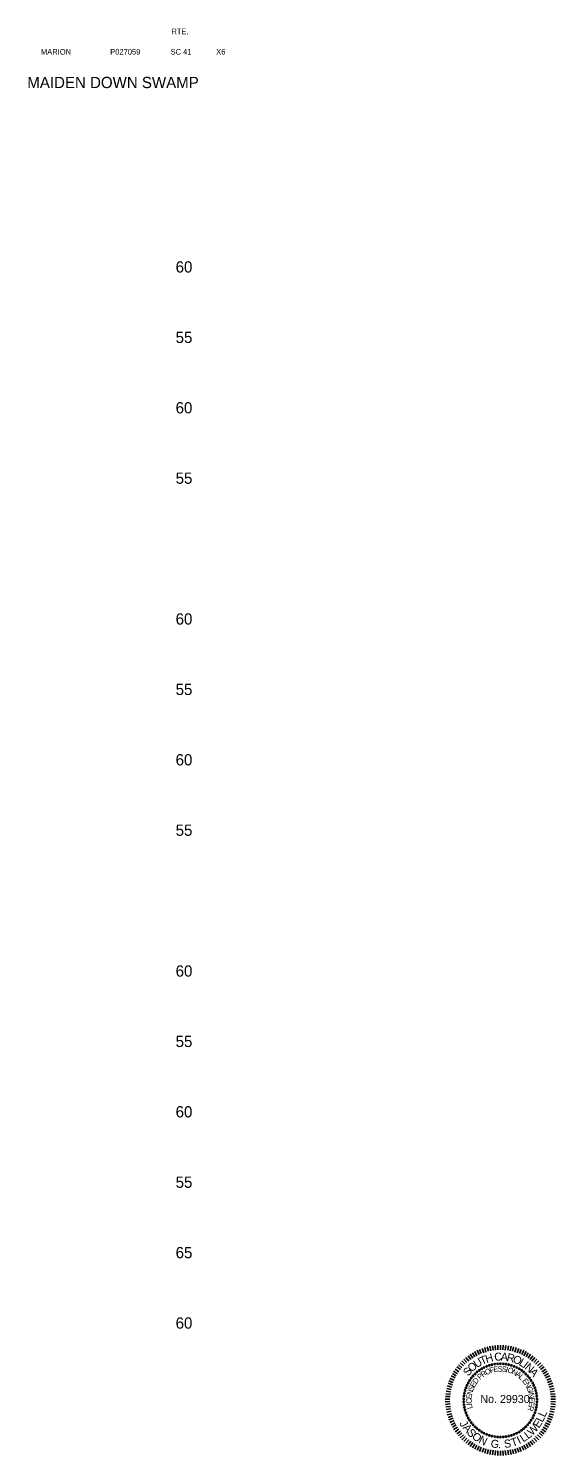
# Model space of a CAD drawing. Extents: x 1001 to 1184, y 1001 to 1447.
# Drawn here: x 1146.5 to 1183.9, y 1001 to 1102.3 of the extents above; entities that cross this region are included whole.
import ezdxf

# ---------------------------------------------------------------- set-up
doc = ezdxf.new("R2010")
doc.units = 0
for name, color, linetype in [('RD_HC_Cl', 7, 'Continuous'), ('RD_SHT_TX', 7, 'Continuous'), ('RD_TX_PEShield', 7, 'Continuous'), ('RD_XS_TX_Elev_EX', 7, 'Continuous')]:
    doc.layers.add(name, color=color, linetype=linetype)

# ---------------------------------------------------------------- blocks, each defined once
blk = doc.blocks.new('STILLWELL')
at = {"layer": 'RD_TX_PEShield'}
for p, q in [((-21.1, 28.1), (-23, 30.7)), ((-19.7, 29.1), (-21.5, 31.8)), ((-18.2, 30), (-19.9, 32.8)), ((-16.7, 30.8), (-18.2, 33.7)), ((-15.1, 31.6), (-16.5, 34.6)), ((-13.6, 32.3), (-14.8, 35.3)), ((-11.9, 32.9), (-13, 36)), ((-10.3, 33.4), (-11.2, 36.6)), ((-8.6, 33.9), (-9.4, 37.1)), ((-6.9, 34.3), (-7.5, 37.5)), ((-5.2, 34.6), (-5.7, 37.8)), ((-3.5, 34.8), (-3.8, 38)), ((-1.8, 34.9), (-1.9, 38.2)), ((0, 34.9), (0, 38.2)), ((1.7, 34.9), (1.9, 38.2)), ((3.4, 34.8), (3.7, 38)), ((5.2, 34.6), (5.6, 37.8)), ((6.9, 34.3), (7.5, 37.5)), ((8.6, 33.9), (9.3, 37.1)), ((10.2, 33.4), (11.2, 36.6)), ((11.9, 32.9), (13, 36)), ((13.5, 32.3), (14.7, 35.3)), ((15.1, 31.6), (16.5, 34.6)), ((16.6, 30.8), (18.2, 33.7)), ((18.2, 30), (19.8, 32.8)), ((19.6, 29.1), (21.4, 31.8)), ((21.1, 28.1), (23, 30.7)), ((-29.5, 19.4), (-32.2, 21.3)), ((-28.5, 20.9), (-31.1, 22.8)), ((-27.4, 22.2), (-29.9, 24.3)), ((-26.3, 23.5), (-28.7, 25.7)), ((-25.1, 24.7), (-27.4, 27.1)), ((-23.8, 25.9), (-26, 28.4)), ((-22.5, 27), (-24.5, 29.6)), ((22.4, 27), (24.5, 29.6)), ((23.8, 25.9), (25.9, 28.4)), ((25, 24.7), (27.3, 27.1)), ((26.2, 23.5), (28.6, 25.7)), ((27.4, 22.2), (29.9, 24.3)), ((28.5, 20.9), (31.1, 22.8)), ((29.5, 19.4), (32.2, 21.3)), ((-34.1, 10.2), (-37.2, 11.2)), ((-33.6, 11.8), (-36.6, 12.9)), ((-32.9, 13.4), (-35.9, 14.7)), ((-32.2, 15), (-35.1, 16.4)), ((-31.4, 16.5), (-34.2, 18.1)), ((-30.5, 18), (-33.3, 19.7)), ((30.4, 18), (33.2, 19.7)), ((31.3, 16.5), (34.2, 18.1)), ((32.1, 15), (35.1, 16.4)), ((32.9, 13.4), (35.9, 14.7)), ((33.5, 11.8), (36.6, 12.9)), ((34.1, 10.2), (37.2, 11.2)), ((-35.9, -0.1), (-39.2, 0)), ((-35.8, 1.7), (-39.1, 1.9)), ((-35.6, 3.4), (-38.9, 3.8)), ((-35.4, 5.1), (-38.6, 5.7)), ((-35.1, 6.8), (-38.2, 7.5)), ((-34.6, 8.5), (-37.8, 9.4)), ((34.6, 8.5), (37.7, 9.4)), ((35, 6.8), (38.2, 7.5)), ((35.3, 5.1), (38.5, 5.7)), ((35.6, 3.4), (38.8, 3.8)), ((35.7, 1.7), (39, 1.9)), ((35.8, -0.1), (39.1, 0)), ((-35.9, -1.8), (-39.2, -1.9)), ((-35.8, -3.5), (-39.1, -3.8)), ((-35.6, -5.3), (-38.9, -5.6)), ((-35.4, -7), (-38.6, -7.5)), ((-35.1, -8.7), (-38.2, -9.4)), ((35, -8.7), (38.2, -9.4)), ((35.3, -7), (38.5, -7.5)), ((35.6, -5.3), (38.8, -5.6)), ((35.7, -3.5), (39, -3.8)), ((35.8, -1.8), (39.1, -1.9)), ((-34.6, -10.4), (-37.8, -11.2)), ((-34.1, -12), (-37.2, -13)), ((-33.6, -13.6), (-36.6, -14.8)), ((-32.9, -15.3), (-35.9, -16.6)), ((-32.2, -16.8), (-35.1, -18.3)), ((-31.4, -18.4), (-34.2, -19.9)), ((-30.5, -19.9), (-33.3, -21.6)), ((30.4, -19.9), (33.2, -21.6)), ((31.3, -18.4), (34.2, -19.9)), ((32.1, -16.8), (35.1, -18.3)), ((32.9, -15.3), (35.9, -16.6)), ((33.5, -13.6), (36.6, -14.8)), ((34.1, -12), (37.2, -13)), ((34.6, -10.4), (37.7, -11.2)), ((-29.5, -21.3), (-32.2, -23.2)), ((-28.5, -22.7), (-31.1, -24.7)), ((-27.4, -24.1), (-29.9, -26.2)), ((-26.3, -25.4), (-28.7, -27.6)), ((-25.1, -26.6), (-27.4, -28.9)), ((-23.8, -27.8), (-26, -30.2)), ((-22.5, -28.9), (-24.5, -31.4)), ((-21.1, -29.9), (-23, -32.6)), ((21.1, -29.9), (23, -32.6)), ((22.4, -28.9), (24.5, -31.4)), ((23.8, -27.8), (25.9, -30.2)), ((25, -26.6), (27.3, -28.9)), ((26.2, -25.4), (28.6, -27.6)), ((27.4, -24.1), (29.9, -26.2)), ((28.5, -22.7), (31.1, -24.7)), ((29.5, -21.3), (32.2, -23.2)), ((-19.7, -30.9), (-21.5, -33.7)), ((-18.2, -31.8), (-19.9, -34.7)), ((-16.7, -32.7), (-18.2, -35.6)), ((-15.1, -33.5), (-16.5, -36.4)), ((-13.6, -34.1), (-14.8, -37.2)), ((-11.9, -34.8), (-13, -37.8)), ((-10.3, -35.3), (-11.2, -38.4)), ((-8.6, -35.8), (-9.4, -38.9)), ((-6.9, -36.1), (-7.5, -39.3)), ((-5.2, -36.4), (-5.7, -39.7)), ((-3.5, -36.6), (-3.8, -39.9)), ((-1.8, -36.8), (-1.9, -40)), ((0, -36.8), (0, -40.1)), ((1.7, -36.8), (1.9, -40)), ((3.4, -36.6), (3.7, -39.9)), ((5.2, -36.4), (5.6, -39.7)), ((6.9, -36.1), (7.5, -39.3)), ((8.6, -35.8), (9.3, -38.9)), ((10.2, -35.3), (11.2, -38.4)), ((11.9, -34.8), (13, -37.8)), ((13.5, -34.1), (14.7, -37.2)), ((15.1, -33.5), (16.5, -36.4)), ((16.6, -32.7), (18.2, -35.6)), ((18.2, -31.8), (19.8, -34.7)), ((19.6, -30.9), (21.4, -33.7))]:
    blk.add_line(p, q, dxfattribs=at)
for centre in [(-15, 20.4), (-13.3, 21.5), (-11.6, 22.4), (-9.8, 23.2), (-7.9, 23.9), (-6, 24.4), (-4, 24.8), (-2, 25), (0, 25.1), (2, 25), (3.9, 24.8), (5.9, 24.4), (7.8, 23.9), (9.7, 23.2), (11.5, 22.4), (13.3, 21.5), (15, 20.4), (-23.8, 9.7), (-22.9, 11.5), (-21.9, 13.2), (-20.7, 14.9), (-19.5, 16.4), (-18.1, 17.8), (-16.6, 19.2), (16.5, 19.2), (18, 17.8), (19.4, 16.4), (20.7, 14.9), (21.8, 13.2), (22.9, 11.5), (23.7, 9.7), (-26.1, 0.1), (-25.9, 2.1), (-25.6, 4), (-25.1, 6), (-24.5, 7.9), (24.5, 7.9), (25.1, 6), (25.5, 4), (25.8, 2.1), (26, 0.1), (-26.1, -1.9), (-25.9, -3.9), (-25.6, -5.9), (-25.1, -7.8), (-24.5, -9.7), (24.5, -9.7), (25.1, -7.8), (25.5, -5.9), (25.8, -3.9), (26, -1.9), (-23.8, -11.6), (-22.9, -13.4), (-21.9, -15.1), (-20.7, -16.7), (-19.5, -18.3), (-18.1, -19.7), (18, -19.7), (19.4, -18.3), (20.7, -16.7), (21.8, -15.1), (22.9, -13.4), (23.7, -11.6), (-16.6, -21), (-15, -22.2), (-13.3, -23.3), (-11.6, -24.3), (-9.8, -25.1), (-7.9, -25.8), (-6, -26.3), (-4, -26.7), (-2, -26.9), (0, -27), (2, -26.9), (3.9, -26.7), (5.9, -26.3), (7.8, -25.8), (9.7, -25.1), (11.5, -24.3), (13.3, -23.3), (15, -22.2), (16.5, -21)]:
    blk.add_circle(centre, 0.49, dxfattribs=at)
for s, height, rotation, p in [('T', 5.68, 23.5044, (-13.2, 24.1)), ('H', 5.68, 16.1357, (-9.9, 25.6)), ('C', 5.68, 4.076, (-4.2, 27.1)), ('A', 5.68, 355.3651, (0.1, 27.4)), ('R', 5.68, 347.3188, (4.1, 27.1)), ('O', 5.68, 338.6079, (8.3, 26.2)), ('S', 5.68, 49.6435, (-22.9, 15.8)), ('O', 5.68, 41.5972, (-20.4, 18.8)), ('U', 5.68, 32.2152, (-16.9, 21.8)), ('O', 3.92, 24.9735, (-10, 16.9)), ('F', 3.92, 15.9995, (-7.1, 18.3)), ('E', 3.92, 8.9511, (-4.7, 19)), ('S', 3.92, 1.2546, (-1.9, 19.4)), ('S', 3.92, 353.558, (0.8, 19.5)), ('I', 3.92, 345.8615, (3.5, 19.2)), ('O', 3.92, 342.6583, (4.7, 19)), ('N', 3.92, 333.6842, (7.7, 18)), ('L', 5.68, 329.226, (12.6, 24.4)), ('I', 5.68, 322.5218, (15.5, 22.8)), ('N', 5.68, 319.1729, (16.8, 21.8)), ('A', 5.68, 310.4621, (20.1, 19)), ('E', 3.92, 60.2341, (-18.5, 7.9)), ('D', 3.92, 52.5376, (-17.1, 10.3)), ('P', 3.92, 41.0022, (-14.5, 13.5)), ('R', 3.92, 33.3057, (-12.5, 15.3)), ('A', 3.92, 325.3521, (10.4, 16.7)), ('L', 3.92, 317.6555, (12.6, 15.1)), ('E', 3.92, 308.0396, (15.1, 12.8)), ('N', 3.92, 300.343, (16.8, 10.6)), ('C', 3.92, 92.2915, (-20.4, -3.2)), ('E', 3.92, 83.9594, (-20.5, -0.2)), ('N', 3.92, 76.2628, (-20.2, 2.5)), ('S', 3.92, 67.9307, (-19.5, 5.4)), ('G', 3.92, 292.0109, (18.3, 8.1)), ('I', 3.92, 283.0368, (19.5, 5.1)), ('N', 3.92, 279.8336, (19.8, 4)), ('E', 3.92, 271.5014, (20.3, 1.1)), ('I', 3.92, 95.4947, (-20.2, -4.3)), ('L', 3.92, 101.9075, (-19.7, -6.6)), ('R', 3.92, 256.1083, (20.1, -4.4)), ('E', 3.92, 263.8049, (20.4, -1.7)), ('L', 5.68, 65.098, (31.6, -13.3)), ('J', 5.68, 299.033, (-29.4, -17.3)), ('A', 5.68, 310.5887, (-27.2, -20.6)), ('W', 5.68, 47.0518, (22.6, -26.4)), ('E', 5.68, 56.4327, (27.3, -21.1)), ('L', 5.68, 65.098, (30, -16.9)), ('S', 5.68, 310.5887, (-24.3, -24)), ('O', 5.68, 321.0072, (-20.8, -27.4)), ('N', 5.68, 333.4326, (-16, -30.8)), ('G', 5.68, 352.2045, (-7.2, -34.2)), ('S', 5.68, 8.0826, (2.9, -34.8)), ('T', 5.68, 18.9019, (8.5, -33.9)), ('I', 5.68, 25.3991, (13.3, -32.2)), ('L', 5.68, 34.0644, (16.2, -30.9)), ('L', 5.68, 37.6708, (19.6, -28.7)), ('.', 5.68, 0.8698, (-1.8, -34.9))]:
    blk.add_text(s, height=height, rotation=rotation, dxfattribs=at).set_placement(p)
blk.add_text('No. 29930', height=5.68, dxfattribs=at).set_placement((-14.3, -2.8))

msp = doc.modelspace()

# ---------------------------------------------------------------- block references
at = {"layer": 'RD_HC_Cl', "xscale": 0.1, "yscale": 0.10000000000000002}
msp.add_blockref('STILLWELL', (1180, 1005), dxfattribs=at)

# ---------------------------------------------------------------- texts
at = {"layer": 'RD_SHT_TX'}
for s, height, p in [('RTE.', 0.4, (1156.62, 1101.93)), ('MARION', 0.4, (1147.35, 1100.48)), ('P027059', 0.4, (1152.27, 1100.48)), ('SC 41', 0.4, (1156.56, 1100.48)), ('X6', 0.4, (1159.8, 1100.48)), ('MAIDEN DOWN SWAMP', 0.8, (1146.38, 1098.1))]:
    msp.add_text(s, height=height, dxfattribs=at).set_placement(p)
at = {"layer": 'RD_XS_TX_Elev_EX'}
for s, p in [('60', (1156.92, 1085)), ('55', (1156.92, 1080)), ('60', (1156.92, 1075)), ('55', (1156.92, 1070)), ('60', (1156.92, 1060)), ('55', (1156.92, 1055)), ('60', (1156.92, 1050)), ('55', (1156.92, 1045)), ('60', (1156.92, 1035)), ('55', (1156.92, 1030)), ('60', (1156.92, 1025)), ('55', (1156.92, 1020)), ('65', (1156.92, 1015)), ('60', (1156.92, 1010))]:
    msp.add_text(s, height=0.8, dxfattribs=at).set_placement(p)

doc.saveas('drawing.dxf')
